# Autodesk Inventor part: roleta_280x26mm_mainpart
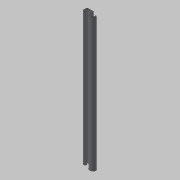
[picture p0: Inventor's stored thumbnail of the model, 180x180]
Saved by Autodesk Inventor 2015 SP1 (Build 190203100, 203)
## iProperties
Created: 2015-06
Part Number: roleta_280x26mm_mainpart
Material: Generic
Document SubType Name: Modeling
Designer: uidn2323
Density: 1 g/cm^3
Appearance: Default
Author: uidn2323
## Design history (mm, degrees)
sketch "Sketch9"
  geometry: L1 (13.17, -3.952)-(13.17, -2.165); L2 (11.706, -0.701)-(7.314, -0.701); L3 (2.499, -4.802)-(19.933, -4.802); L4 (15.979, -0.698)-(15.979, -4.198); L5 (0.24, -4.8)-(0.24, -0.701); L6 (13.17, 2.227)-(3.168, 2.227); L7 (7.314, -0.701)-(5.516, -0.701); L8 (5.516, -0.701)-(3.476, -0.701); L9 (3.476, -0.701)-(3.476, -1.809); L10 (3.24, -4.8)-(3.24, -4.453); L11 (2.134, -4.8)-(19.568, -4.8); L12 (26.346, -4.113)-(23.067, -2.32); L13 (8.827, -1.117)-(12.721, -1.117); L14 (26.346, -4.113)-(26.346, -7.113); L15 (19.933, -4.8)-(19.933, -4.453); A1 r 2.928 centre (13.051, -0.698) between (15.979, -0.698) and (13.17, 2.227); A2 r 1.464 centre (11.706, -2.165) between (13.17, -2.165) and (11.706, -0.701); A3 r 2.928 centre (3.168, -0.701) between (3.168, 2.227) and (0.24, -0.701); A4 r 4 centre (19.933, -4.805) between (15.979, -4.198) and (23.067, -2.32); A5 r 6.816 centre (19.933, -4.805) between (13.17, -3.952) and (26.346, -7.113); A6 r 3 centre (3.24, -4.8) between (0.24, -4.8) and (3.476, -1.809); 4 further points
  constraints: 31 end point, 12 point on circle, 7 horizontal, 6 centre point, 4 tangent, 4 vertical, 2 coincident, 1 perpendicular
  dimensions: "d179" = 6.816 radius of A5; "d180" = 4 radius of A4; "d181" = 2.928 radius of A1; "d182" = 10.00212 distance of L6.start L6.end; "d183" = 2.928 radius of A3; "d184" = 1.464 radius of A2; "d185" = 4.392 distance of L2.start L2.end; "d186" = 2.92801 distance between parallel lines of L6 L2; "d187" = 3 radius of A6
extrude "Extrusion3" join sketch "Sketch9" distance "d189" = 278; taper "d190" = 0 deg
sketch "Sketch10"
  geometry: L1 (13.17, -3.952)-(13.17, -2.165); L2 (11.706, -0.701)-(7.314, -0.701); L3 (2.499, -4.802)-(19.933, -4.802); L4 (15.979, -0.698)-(15.979, -4.198); L5 (0.24, -4.8)-(0.24, -0.701); L6 (13.17, 2.227)-(3.168, 2.227); L7 (7.314, -0.701)-(5.516, -0.701); L8 (5.516, -0.701)-(3.476, -0.701); L9 (3.476, -0.701)-(3.476, -1.809); L10 (3.24, -4.8)-(3.24, -4.453); L11 (23.029, -2.299)-(23.039, -2.285); L12 (2.134, -4.8)-(19.568, -4.8); L13 (26.346, -4.113)-(23.029, -2.299); L14 (26.346, -4.113)-(26.346, -7.113); L15 (19.933, -4.8)-(19.933, -4.453); A1 r 2.928 centre (13.051, -0.698) between (15.979, -0.698) and (13.17, 2.227); A2 r 1.464 centre (11.706, -2.165) between (13.17, -2.165) and (11.706, -0.701); A3 r 2.928 centre (3.168, -0.701) between (3.168, 2.227) and (0.24, -0.701); A4 r 4 centre (19.933, -4.805) between (15.979, -4.198) and (23.039, -2.285); A5 r 6.816 centre (19.933, -4.805) between (13.17, -3.952) and (26.346, -7.113); A6 r 3 centre (3.24, -4.8) between (0.24, -4.8) and (3.476, -1.809); 1 further point
  constraints: 31 end point, 12 point on circle, 6 centre point, 6 horizontal, 4 tangent, 4 vertical, 2 coincident, 1 perpendicular
  dimensions: "d202" = 6.816 radius of A5; "d203" = 4 radius of A4; "d204" = 2.928 radius of A1; "d205" = 10.00212 distance of L6.start L6.end; "d206" = 2.928 radius of A3; "d207" = 1.464 radius of A2; "d208" = 4.392 distance of L2.start L2.end; "d209" = 2.92801 distance between parallel lines of L6 L2; "d210" = 3 radius of A6
sketch "Sketch12"
  geometry: L1 (-0.24, -4.8)-(-0.24, -0.701); L2 (-13.17, -3.952)-(-13.17, -2.165); L3 (-15.979, -0.698)-(-15.979, -4.198); L4 (-26.346, -4.113)-(-23.067, -2.32); L5 (-26.346, -4.113)-(-26.346, -7.113); L6 (-11.706, -0.701)-(-7.314, -0.701); L7 (-3.476, -0.701)-(-3.476, -1.809); L8 (-7.314, -0.701)-(-5.516, -0.701); L9 (-5.516, -0.701)-(-3.476, -0.701); L10 (-13.17, 2.227)-(-3.168, 2.227); L11 (-15.179, -0.698)-(-15.179, -4.139); L12 (-24.683, -4.116)-(-25.546, -4.588); L13 (-25.546, -4.588)-(-25.546, -6.969); L14 (-13.97, -4.004)-(-13.97, -2.165); L15 (-11.706, 0.099)-(-7.314, 0.099); L16 (-7.314, 0.099)-(-5.516, 0.099); L17 (-5.516, 0.099)-(-2.676, 0.099); L18 (-2.676, 0.099)-(-2.676, -2.674); L19 (-1.04, -4.8)-(-1.04, -0.701); L20 (-3.168, 1.427)-(-13.153, 1.427); A1 r 2.928 centre (-3.168, -0.701) between (-0.24, -0.701) and (-3.168, 2.227); A2 r 3 centre (-3.24, -4.8) between (-3.476, -1.809) and (-0.24, -4.8); A3 r 1.464 centre (-11.706, -2.165) between (-11.706, -0.701) and (-13.17, -2.165); A4 r 2.928 centre (-13.051, -0.698) between (-13.17, 2.227) and (-15.979, -0.698); A5 r 4 centre (-19.933, -4.805) between (-23.067, -2.32) and (-15.979, -4.198); A6 r 6.816 centre (-19.933, -4.805) between (-26.346, -7.113) and (-13.17, -3.952); A7 r 4.8 centre (-19.933, -4.805) between (-24.683, -4.116) and (-15.179, -4.139); A8 r 6.016 centre (-19.933, -4.805) between (-25.546, -6.969) and (-13.97, -4.004); A9 r 2.264 centre (-11.706, -2.165) between (-11.706, 0.099) and (-13.97, -2.165); A10 r 2.2 centre (-3.24, -4.8) between (-2.676, -2.674) and (-1.04, -4.8); A11 r 2.128 centre (-3.168, -0.701) between (-1.04, -0.701) and (-3.168, 1.427); A12 r 2.128 centre (-13.051, -0.698) between (-13.153, 1.427) and (-15.179, -0.698); 2 further points
  constraints: 40 end point, 24 point on circle, 12 centre point, 1 coincident, 15 other
  dimensions: "d225" = 0.8 radial gap between concentric circles of A4 A12
extrude "Extrusion5" cut sketch "Sketch12" stored distance "d226" = 10; taper "d227" = 0 deg
body "Solid1"
other parameters: "d122" = 6.83405, "d123" = 4.99923
